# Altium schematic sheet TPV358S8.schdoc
size 127 x 101 mm
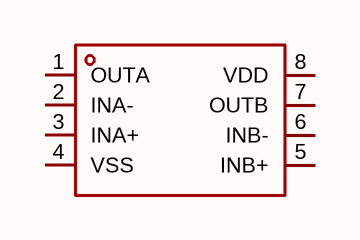
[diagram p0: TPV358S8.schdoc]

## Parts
U?  tpv358s8  [SOP-8_L4.9-W3.9-P1.27-LS6.0-BL]  (value not drawn)

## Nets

Not connected (* = marked no-connect by the designer): U? 1(OUTA) 2(INA-) 3(INA+) 4(VSS) 5(INB+) 6(INB-) 7(OUTB) 8(VDD)

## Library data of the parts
U? = tpv358s8: 放大器数:2;轨到轨:轨到轨输入,轨到轨输出;增益带宽积(GBW):1MHz;输入失调电压(Vos):5mV;压摆率(SR):600V/ms;输入偏置电流(Ib):10pA;; Manufacturer: TECH PUBLIC(台舟); AddInBom: yes; ModelId: 75c24a7891ee4dd6bdac16a7163ff87e; ModelName: SOP-8_L4.9-W3.9-P1.27-LS6.0-BL-1; ModelTransform: 192.913,236.22,0,0,0,0,-0.393,2.749,0; Number of Channels: 2; Maximum Power Supply Range (Vdd-Vss): 7V; Gain Bandwidth Product: 1MHz; Vos - Input Offset Voltage: 5mV; Input Offset Voltage Drift(Vos TC): 2uV/℃; Ib - Input Bias Current: 10pA; Input Voltage Noise Density: 20nV/√Hz@10kHz; Common Mode Rejection Ratio(CMRR): 80dB; Quiescent Current: 80uA; Output Current: 20mA; Single supply: 2.2V~5.5V; Dual Supply: 1.1V~2.75V；-2.75V~-1.1V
